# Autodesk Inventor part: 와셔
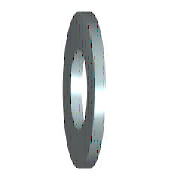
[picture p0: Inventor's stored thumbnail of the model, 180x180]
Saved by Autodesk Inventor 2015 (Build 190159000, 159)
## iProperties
Created: 2012-02
Part Number: 와셔
Material: 강철, 연강
Description: 평면 와셔
Document SubType Name: Modeling
Standard: KS B 1326
Designer: mduedu
Standards Organization: KS
Language: ko-KR
Size Designation: 8x15.5
Categories: <MemberInstance><Categories><Category DisplayName="조임쇠" InternalName="e4da775c-781d-43d5-af7c-5136215cf5a6" Mnemonic="FSTN"><Category DisplayName="와셔" InternalN
Density: 1 g/cm^3
Appearance: 파란색 - 벽 페인트 - 광택
IsCustomPart: 1
Author: mduedu
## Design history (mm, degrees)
sketch "스케치"
  geometry: C1 r 7.75 at (0, 0); C2 r 4.2 at (0, 0); 1 further point
  constraints: 2 centre point, 2 coincident
  dimensions: "d0" = 8.4 diameter of C2 (= SD1); "d1" = 15.5 diameter of C1 (= SD2)
extrude "본체" new body sketch "스케치" distance "d2" = 1.6 (= SD); taper "d3" = 0 deg
workaxis "Work Axis1"
workplane "Work Plane1"
body "Solid1"
other parameters: "SD1" = 8.4 [user parameter; used in 1 equation term], "SD2" = 15.5 [user parameter; used in 1 equation term], "SD" = 1.6 [user parameter; used in 1 equation term], "d4" = 0, "d5" = 0, "d6" = 0, "d7" = 0, "NND" = 8 [user parameter]
